(* Logix 5000 project; controller Electronic_Displays vendor 1 type 14 code 65 rev 17.4; software revision 17.01 *)
// Electronic Displays, Inc.
// Test PLC for Anybus Communicator

TASK MainTask (continuous, watchdog 500 ms) : MainProgram

MODULES
   Controller : vendor 1 type 14 code 65 (CompactLogixL35Controller 0, rev 17.4)
      LocalENB : 1769-L35E Ethernet Port (CompactLogixL35Ethernet 1, rev 17.2)
         LEDSIGN : ETHERNET-MODULE (Ethernet 192.168.1.11, rev 1.1, Output RPI 10 ms)   // RTA
      Local : CompactBus (CompactVirtualAdapter 3, rev 17.2, Input RPI 5 ms)
END_MODULES

TYPE LEDSIGN :
STRUCT
   Address : STRING;   // "00"=all signs "01"=sign address 1 "02"=sign address 2 etc... per protocol [must be two digits]
   CommandCode : STRING;   // "A"=write restart "B"=write variable "C"=special "D"=write no restart
   FileLabel : STRING;   // Default is = A
   Text1Message : STRING;   // Actual Text Line 1
   Text2Message : STRING;   // Actual Text Line 2
   Text3Message : STRING;   // Actual Text Line 3
   Text4Message : STRING;   // Actual Text Line 4
   TextFont : STRING;   // "0"=SS7 "1"=SF7 "2"=SF10 "3"=SS16 "4"=SF16
   TextColor : STRING;   // "0"=Red "1"=Green "2"=Yellow "3"=Rainbow
   TextAlign : STRING;   // "M"=middle line "T"=top line "B"=bottom line "F"=fill (best for variables) "L"=left "R"=right
   TextAttribute : STRING;   // "0"=flashing off "1"=flashing on "2"=wide off "3"=wide on "4"=bold off "5"=bold on
   TextEffect : STRING;   // "S"=scrolls "H"=hold "F"=flash "A"=slide up "B"=slide down "C"=slide left "D"=slide right "a"=roll up "b"=roll down "c"=roll left "d"=roll right
   TextSpeed : STRING;   // Options = 1 - 8, 3:Default 1=Fast 8=Slow
   TextPause : STRING;   // Options = 00 - 99, 02:Default defined in seconds [must be two digits] if not will not work!
   Variable1Name : STRING;   // Name of variable Default is = U
   Variable2Name : STRING;   // Name of variable Default is = V
   Variable3Name : STRING;   // Name of variable Default is = W
   Variable4Name : STRING;   // Name of variable Default is = X
   Variable1Value : STRING;   // Actual Variable1 to be Sent (text format)
   Variable2Value : STRING;   // Actual Variable2 to be Sent (text format)
   Variable3Value : STRING;   // Actual Variable3 to be Sent (text format)
   Variable4Value : STRING;   // Actual Variable4 to be Sent (text format)
   VariableFont : STRING;   // "0"=SS7 "1"=SF7 "2"=SF10 "3"=SS16 "4"=SF16
   VariableColor : STRING;   // "0"=Red "1"=Green "2"=Yellow "3"=Rainbow
   VariableAttribute : STRING;   // "0"=flashing off "1"=flashing on "2"=wide off "3"=wide on "4"=bold off "5"=bold on
   Packet1Sent : STRING;   // The actual packet sent to the sign. (Packet1)
   Packet2Sent : STRING;   // The actual packet sent to the sign. (Packet2)
   Packet3Sent : STRING;   // The actual packet sent to the sign. (Packet3)
   Packet4Sent : STRING;   // The actual packet sent to the sign. (Packet4)
   Packet5Sent : STRING;   // The actual packet sent to the sign. (Packet5)
   Packet6Sent : STRING;   // The actual packet sent to the sign. (Packet6)
   ExpertPacket1 : STRING;   // Raw Packet1 to be sent to sign for the expert users. (82 Characters max)
   ExpertPacket2 : STRING;   // Raw Packet2 to be sent to sign for the expert users. (82 Characters max)
   ExpertPacket3 : STRING;   // Raw Packet3 to be sent to sign for the expert users. (82 Characters max)
   ExpertPacket4 : STRING;   // Raw Packet4 to be sent to sign for the expert users. (82 Characters max)
   ExpertPacket5 : STRING;   // Raw Packet5 to be sent to sign for the expert users. (82 Characters max)
   ExpertPacket6 : STRING;   // Raw Packet6 to be sent to sign for the expert users. (82 Characters max)
END_STRUCT
END_TYPE

TYPE NUMSIGN :
STRUCT
   Address : STRING;   // "01"=sign address 1 "02"=sign address 2 etc... per protocol [must be two digits]
   NumberValue : DINT;   // Actual Number to Send to Sign (DINT Format)
   PacketSent : STRING;   // The actual packet sent to the sign.
END_STRUCT
END_TYPE

ADD_ON_INSTRUCTION ExpertSign   (* revision 1.0, ExecuteEnableInFalse *)
// Expert Mode
// Send Your Own
// Packets
// Revision note:
// Original Release
// 11-01-2012
// c.elston
VAR_IN_OUT
   ExpertPacket1 : STRING; {required}   // Raw Packet1 to be sent to sign for the expert users. (82 Characters max)
   ExpertPacket2 : STRING; {required}   // Raw Packet2 to be sent to sign for the expert users. (82 Characters max)
   ExpertPacket3 : STRING; {required}   // Raw Packet3 to be sent to sign for the expert users. (82 Characters max)
   ExpertPacket4 : STRING; {required}   // Raw Packet4 to be sent to sign for the expert users. (82 Characters max)
   ExpertPacket5 : STRING; {required}   // Raw Packet5 to be sent to sign for the expert users. (82 Characters max)
   ExpertPacket6 : STRING; {required}   // Raw Packet6 to be sent to sign for the expert users. (82 Characters max)
END_VAR
VAR_OUTPUT
   EN : BOOL; {visible}   // Instruction Interface Enable Bit
   DN : BOOL; {visible}   // Instruction Interface Done Bit
   ER : BOOL; {visible}   // Instruction Interface Error Bit
   IP : BOOL; {visible}   // Instruction Interface InProcess Bit
END_VAR
VAR_IN_OUT
   map_SignInput : SINT[32]; {required}   // Ethernet/IP LEDSIGN.I Data I/O Mapping
   map_SignOutput : SINT[496]; {required}   // Ethernet/IP LEDSIGN.O Data I/O Mapping
   Packet1Sent : STRING; {required}   // The actual packet sent to the sign (Packet1)
   Packet2Sent : STRING; {required}   // The actual packet sent to the sign (Packet2)
   Packet3Sent : STRING; {required}   // The actual packet sent to the sign (Packet3)
   Packet4Sent : STRING; {required}   // The actual packet sent to the sign (Packet4)
   Packet5Sent : STRING; {required}   // The actual packet sent to the sign (Packet5)
   Packet6Sent : STRING; {required}   // The actual packet sent to the sign (Packet6)
END_VAR
VAR
   SEQ : DINT;   // Sequence Number
   OktoCycle : BOOL;   // Ok to Cycle
   InCycle : BOOL;   // Incycle
   Error : BOOL;   // Error
   Enabled : BOOL;   // Enable ON Bit
   Done : BOOL;   // Done
   Disabled : BOOL;   // Disabled OFF Bit
   SignNULL : STRING;
   TotalPacketCount : DINT[7];   // Total Character Count
   Select : DINT;   // Packet Array Select
   PacketMax : DINT := 82;   // Max Packet Count
   PacketCount : DINT[7];
   Packet6Offset : DINT;
   Packet5Offset : DINT;
   Packet4Offset : DINT;
   Packet3Offset : DINT;
   Packet2Offset : DINT;
   Packet1Offset : DINT;
   Packet : STRING[7];   // Packet Array to send to sign
   SignExpertPacket6 : STRING;
   SignExpertPacket5 : STRING;
   SignExpertPacket4 : STRING;
   SignExpertPacket3 : STRING;
   SignExpertPacket2 : STRING;
   SignExpertPacket1 : STRING;
END_VAR

ROUTINE EnableInFalse   (* ladder *)
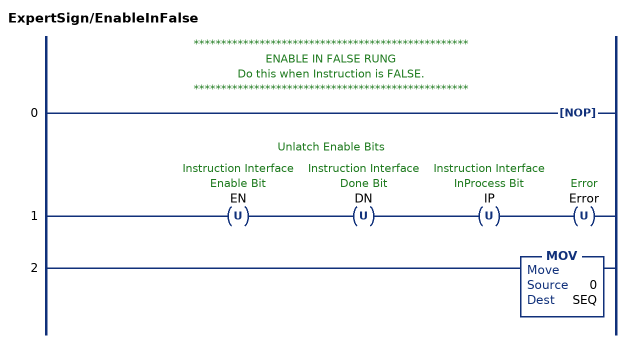
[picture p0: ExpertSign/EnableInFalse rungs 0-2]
   // **************************************************
   // ENABLE IN FALSE RUNG
   // Do this when Instruction is FALSE.
   // **************************************************
   0: NOP();
   // Unlatch Enable Bits
   1: OTU(EN)OTU(DN)OTU(IP)OTU(Error);
   2: MOV(0,SEQ);
END_ROUTINE

ROUTINE Logic   (* ladder *)
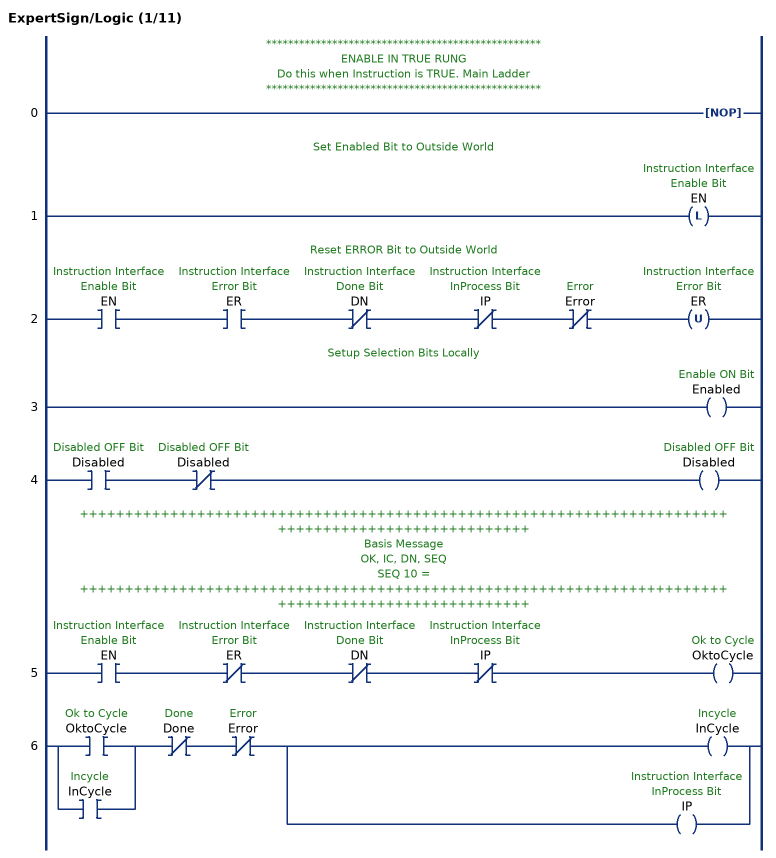
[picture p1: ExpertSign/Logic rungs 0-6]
   // **************************************************
   // ENABLE IN TRUE RUNG
   // Do this when Instruction is TRUE. Main Ladder
   // **************************************************
   0: NOP();
   // Set Enabled Bit to Outside World
   1: OTL(EN);
   // Reset ERROR Bit to Outside World
   2: XIC(EN)XIC(ER)XIO(DN)XIO(IP)XIO(Error)OTU(ER);
   // Setup Selection Bits Locally
   3: OTE(Enabled);
   4: XIC(Disabled)XIO(Disabled)OTE(Disabled);
   // ++++++++++++++++++++++++++++++++++++++++++++++++++++++++++++++++++++++++++++++++++++++++++++++++++++
   // Basis Message
   // OK, IC, DN, SEQ
   // SEQ 10 =
   // ++++++++++++++++++++++++++++++++++++++++++++++++++++++++++++++++++++++++++++++++++++++++++++++++++++
   5: XIC(EN)XIO(ER)XIO(DN)XIO(IP)OTE(OktoCycle);
   6: [XIC(OktoCycle) ,XIC(InCycle) ]XIO(Done)XIO(Error)[OTE(InCycle) ,OTE(IP) ];
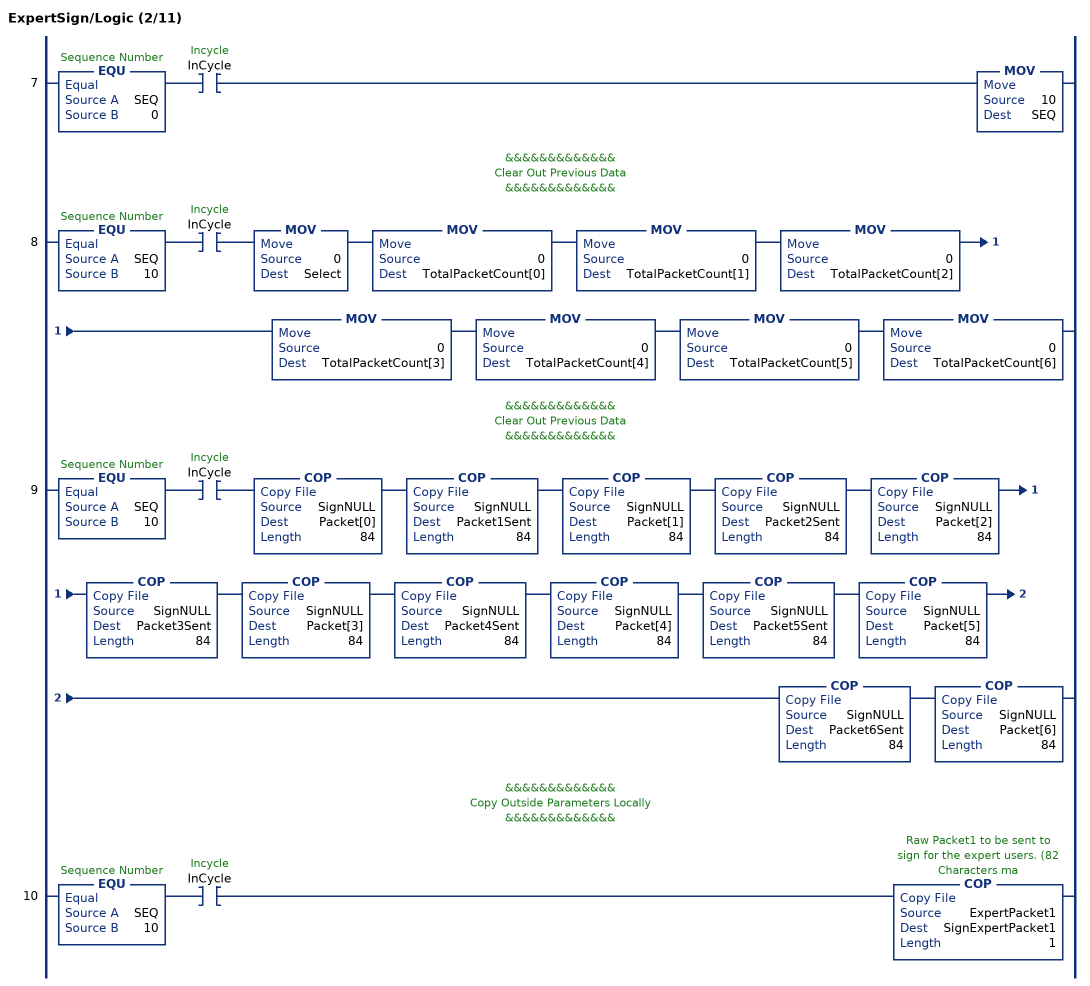
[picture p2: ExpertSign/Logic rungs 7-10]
   7: EQU(SEQ,0)XIC(InCycle)MOV(10,SEQ);
   // &&&&&&&&&&&&&
   // Clear Out Previous Data
   // &&&&&&&&&&&&&
   8: EQU(SEQ,10)XIC(InCycle)MOV(0,Select)MOV(0,TotalPacketCount[0])MOV(0,TotalPacketCount[1])MOV(0,TotalPacketCount[2])MOV(0,TotalPacketCount[3])MOV(0,TotalPacketCount[4])MOV(0,TotalPacketCount[5])MOV(0,TotalPacketCount[6]);
   // &&&&&&&&&&&&&
   // Clear Out Previous Data
   // &&&&&&&&&&&&&
   9: EQU(SEQ,10)XIC(InCycle)COP(SignNULL,Packet[0],84)COP(SignNULL,Packet1Sent,84)COP(SignNULL,Packet[1],84)COP(SignNULL,Packet2Sent,84)COP(SignNULL,Packet[2],84)COP(SignNULL,Packet3Sent,84)COP(SignNULL,Packet[3],84)COP(SignNULL,Packet4Sent,84)COP(SignNULL,Packet[4],84)COP(SignNULL,Packet5Sent,84)COP(SignNULL,Packet[5],84)COP(SignNULL,Packet6Sent,84)COP(SignNULL,Packet[6],84);
   // &&&&&&&&&&&&&
   // Copy Outside Parameters Locally
   // &&&&&&&&&&&&&
   10: EQU(SEQ,10)XIC(InCycle)COP(ExpertPacket1,SignExpertPacket1,1);
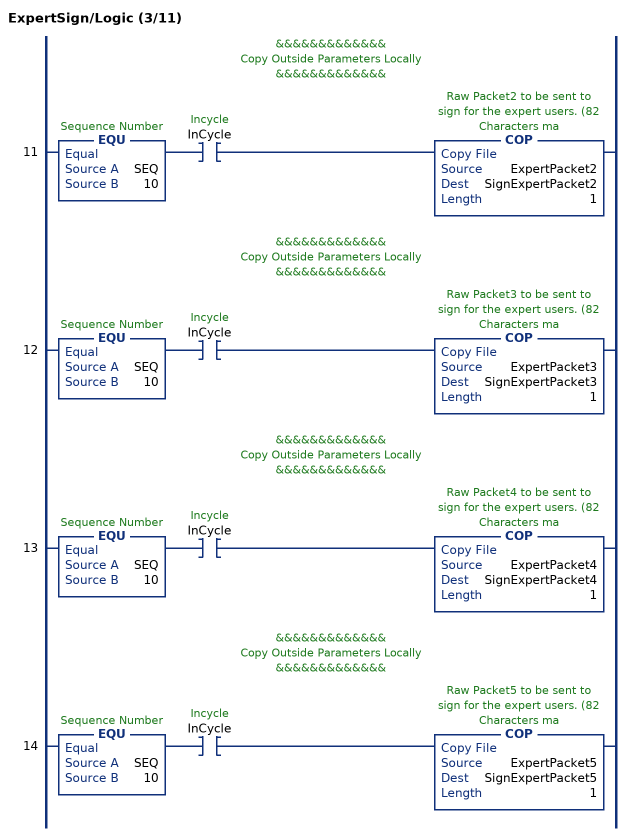
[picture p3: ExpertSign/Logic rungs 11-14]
   // &&&&&&&&&&&&&
   // Copy Outside Parameters Locally
   // &&&&&&&&&&&&&
   11: EQU(SEQ,10)XIC(InCycle)COP(ExpertPacket2,SignExpertPacket2,1);
   // &&&&&&&&&&&&&
   // Copy Outside Parameters Locally
   // &&&&&&&&&&&&&
   12: EQU(SEQ,10)XIC(InCycle)COP(ExpertPacket3,SignExpertPacket3,1);
   // &&&&&&&&&&&&&
   // Copy Outside Parameters Locally
   // &&&&&&&&&&&&&
   13: EQU(SEQ,10)XIC(InCycle)COP(ExpertPacket4,SignExpertPacket4,1);
   // &&&&&&&&&&&&&
   // Copy Outside Parameters Locally
   // &&&&&&&&&&&&&
   14: EQU(SEQ,10)XIC(InCycle)COP(ExpertPacket5,SignExpertPacket5,1);
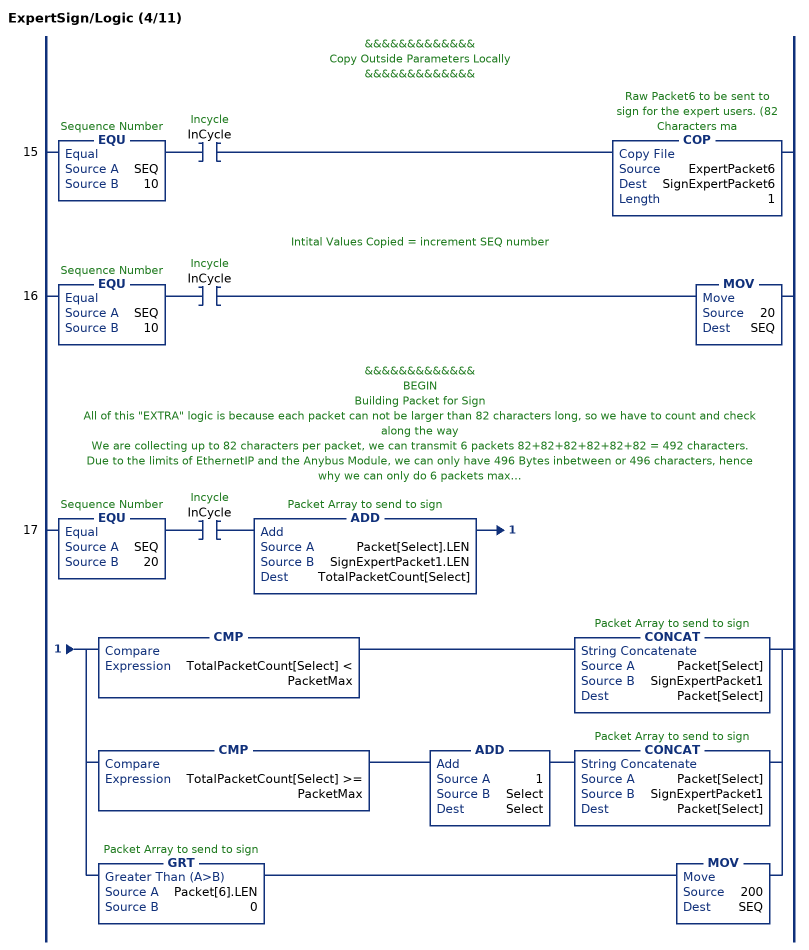
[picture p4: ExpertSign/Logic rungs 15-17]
   // &&&&&&&&&&&&&
   // Copy Outside Parameters Locally
   // &&&&&&&&&&&&&
   15: EQU(SEQ,10)XIC(InCycle)COP(ExpertPacket6,SignExpertPacket6,1);
   // Intital Values Copied = increment SEQ number
   16: EQU(SEQ,10)XIC(InCycle)MOV(20,SEQ);
   // &&&&&&&&&&&&&
   // BEGIN
   // Building Packet for Sign
   // All of this "EXTRA" logic is because each packet can not be larger than 82 characters long, so we have to count and check along the way
   // We are collecting up to 82 characters per packet, we can transmit 6 packets 82+82+82+82+82+82 = 492 characters.
   // Due to the limits of EthernetIP and the Anybus Module, we can only have 496 Bytes inbetween or 496 characters, hence why we can only do 6 packets max.
   // Once we exceed this, we will fault and ERROR trap any windy typing people.
   // In this instruction below, it's so small, we are only using 3 packets max.
   // &&&&&&&&&&&&&
   17: EQU(SEQ,20)XIC(InCycle)ADD(Packet[Select].LEN,SignExpertPacket1.LEN,TotalPacketCount[Select])[CMP(TotalPacketCount[Select] < PacketMax) CONCAT(Packet[Select],SignExpertPacket1,Packet[Select]) ,CMP(TotalPacketCount[Select] >= PacketMax) ADD(1,Select,Select) CONCAT(Packet[Select],SignExpertPacket1,Packet[Select]) ,GRT(Packet[6].LEN,0) MOV(200,SEQ) ];
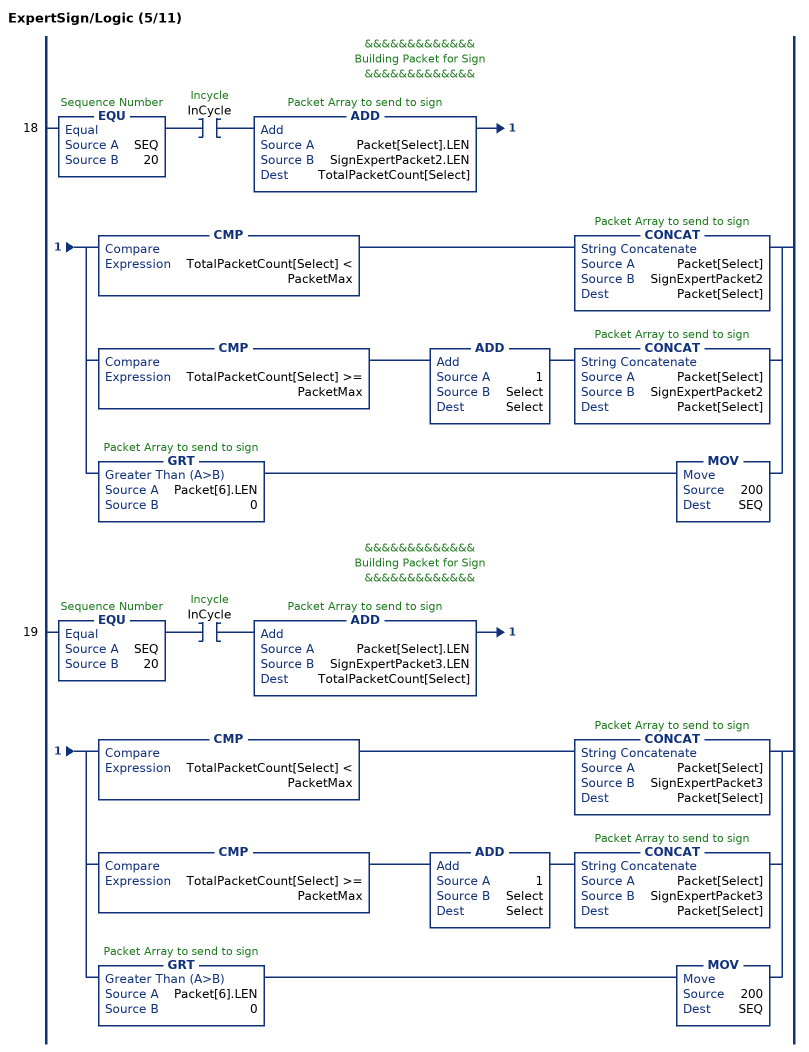
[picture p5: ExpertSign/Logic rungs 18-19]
   // &&&&&&&&&&&&&
   // Building Packet for Sign
   // &&&&&&&&&&&&&
   18: EQU(SEQ,20)XIC(InCycle)ADD(Packet[Select].LEN,SignExpertPacket2.LEN,TotalPacketCount[Select])[CMP(TotalPacketCount[Select] < PacketMax) CONCAT(Packet[Select],SignExpertPacket2,Packet[Select]) ,CMP(TotalPacketCount[Select] >= PacketMax) ADD(1,Select,Select) CONCAT(Packet[Select],SignExpertPacket2,Packet[Select]) ,GRT(Packet[6].LEN,0) MOV(200,SEQ) ];
   // &&&&&&&&&&&&&
   // Building Packet for Sign
   // &&&&&&&&&&&&&
   19: EQU(SEQ,20)XIC(InCycle)ADD(Packet[Select].LEN,SignExpertPacket3.LEN,TotalPacketCount[Select])[CMP(TotalPacketCount[Select] < PacketMax) CONCAT(Packet[Select],SignExpertPacket3,Packet[Select]) ,CMP(TotalPacketCount[Select] >= PacketMax) ADD(1,Select,Select) CONCAT(Packet[Select],SignExpertPacket3,Packet[Select]) ,GRT(Packet[6].LEN,0) MOV(200,SEQ) ];
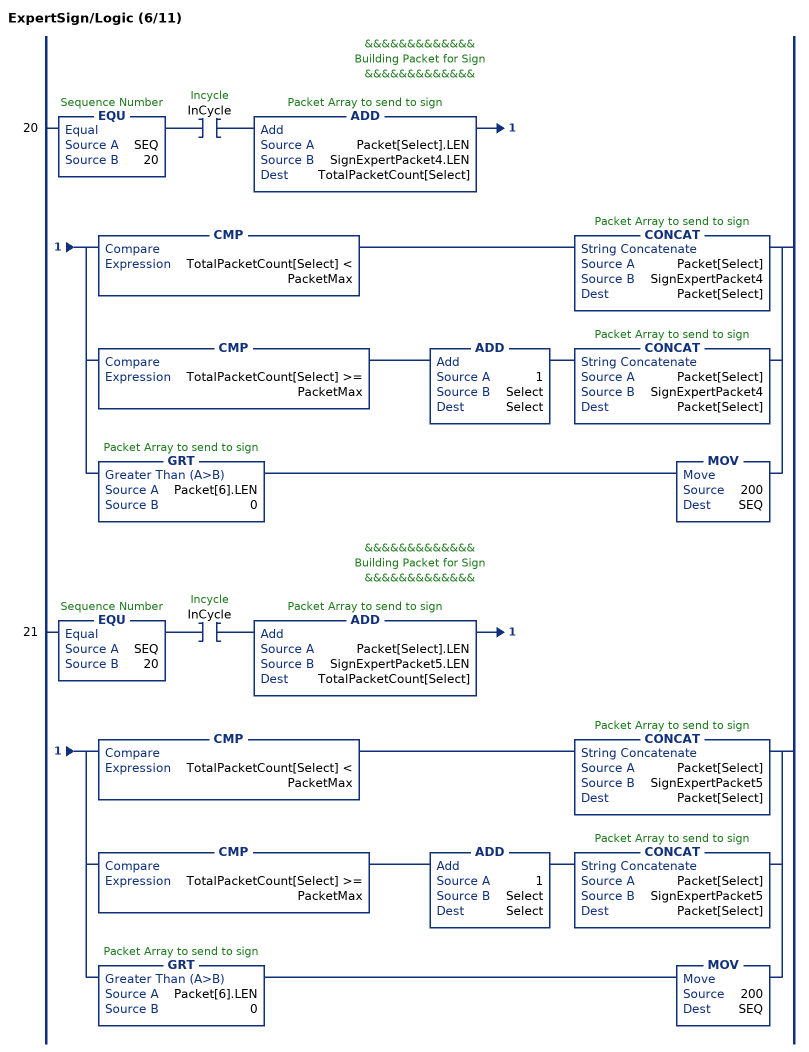
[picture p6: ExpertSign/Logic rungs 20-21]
   // &&&&&&&&&&&&&
   // Building Packet for Sign
   // &&&&&&&&&&&&&
   20: EQU(SEQ,20)XIC(InCycle)ADD(Packet[Select].LEN,SignExpertPacket4.LEN,TotalPacketCount[Select])[CMP(TotalPacketCount[Select] < PacketMax) CONCAT(Packet[Select],SignExpertPacket4,Packet[Select]) ,CMP(TotalPacketCount[Select] >= PacketMax) ADD(1,Select,Select) CONCAT(Packet[Select],SignExpertPacket4,Packet[Select]) ,GRT(Packet[6].LEN,0) MOV(200,SEQ) ];
   // &&&&&&&&&&&&&
   // Building Packet for Sign
   // &&&&&&&&&&&&&
   21: EQU(SEQ,20)XIC(InCycle)ADD(Packet[Select].LEN,SignExpertPacket5.LEN,TotalPacketCount[Select])[CMP(TotalPacketCount[Select] < PacketMax) CONCAT(Packet[Select],SignExpertPacket5,Packet[Select]) ,CMP(TotalPacketCount[Select] >= PacketMax) ADD(1,Select,Select) CONCAT(Packet[Select],SignExpertPacket5,Packet[Select]) ,GRT(Packet[6].LEN,0) MOV(200,SEQ) ];
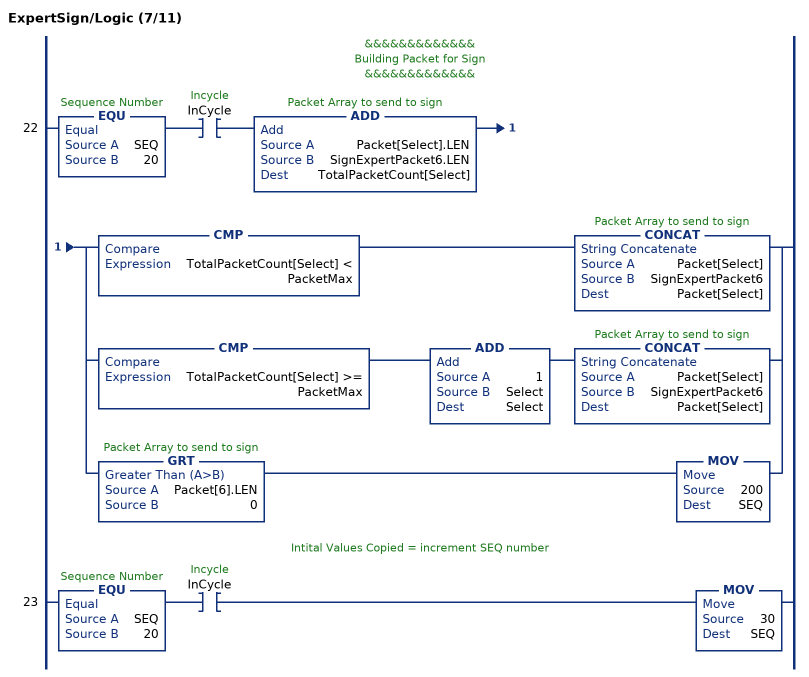
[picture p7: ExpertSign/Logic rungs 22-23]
   // &&&&&&&&&&&&&
   // Building Packet for Sign
   // &&&&&&&&&&&&&
   22: EQU(SEQ,20)XIC(InCycle)ADD(Packet[Select].LEN,SignExpertPacket6.LEN,TotalPacketCount[Select])[CMP(TotalPacketCount[Select] < PacketMax) CONCAT(Packet[Select],SignExpertPacket6,Packet[Select]) ,CMP(TotalPacketCount[Select] >= PacketMax) ADD(1,Select,Select) CONCAT(Packet[Select],SignExpertPacket6,Packet[Select]) ,GRT(Packet[6].LEN,0) MOV(200,SEQ) ];
   // Intital Values Copied = increment SEQ number
   23: EQU(SEQ,20)XIC(InCycle)MOV(30,SEQ);
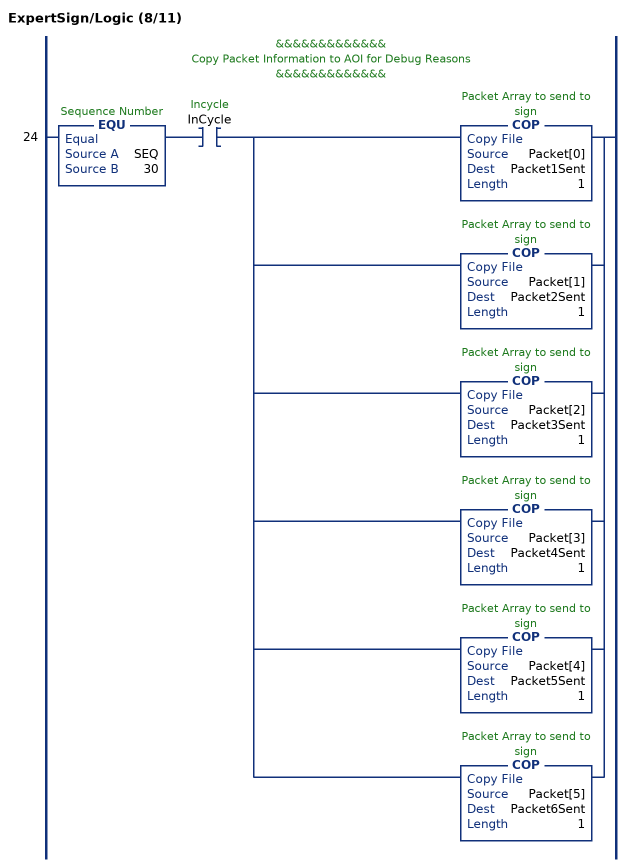
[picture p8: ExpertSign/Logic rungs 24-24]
   // &&&&&&&&&&&&&
   // Copy Packet Information to AOI for Debug Reasons
   // &&&&&&&&&&&&&
   24: EQU(SEQ,30)XIC(InCycle)[COP(Packet[0],Packet1Sent,1) ,COP(Packet[1],Packet2Sent,1) ,COP(Packet[2],Packet3Sent,1) ,COP(Packet[3],Packet4Sent,1) ,COP(Packet[4],Packet5Sent,1) ,COP(Packet[5],Packet6Sent,1) ];
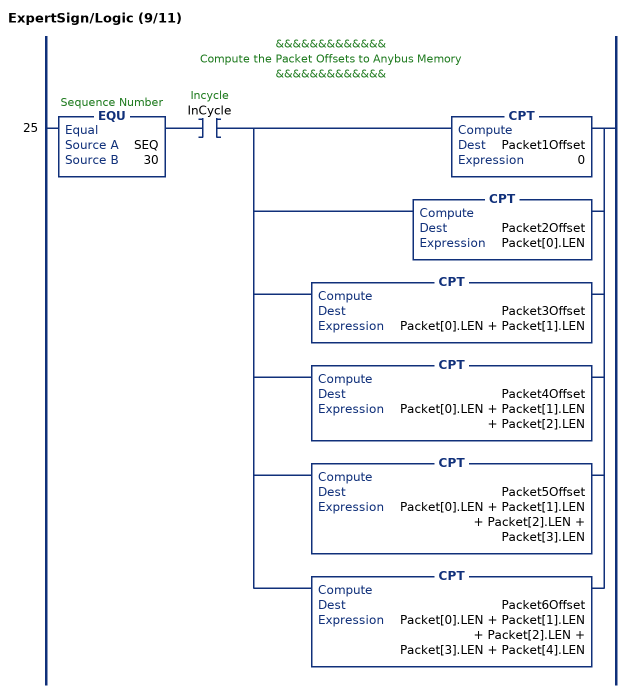
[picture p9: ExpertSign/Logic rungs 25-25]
   // &&&&&&&&&&&&&
   // Compute the Packet Offsets to Anybus Memory
   // &&&&&&&&&&&&&
   25: EQU(SEQ,30)XIC(InCycle)[CPT(Packet1Offset,0) ,CPT(Packet2Offset,Packet[0].LEN) ,CPT(Packet3Offset,Packet[0].LEN + Packet[1].LEN) ,CPT(Packet4Offset,Packet[0].LEN + Packet[1].LEN + Packet[2].LEN) ,CPT(Packet5Offset,Packet[0].LEN + Packet[1].LEN + Packet[2].LEN + Packet[3].LEN) ,CPT(Packet6Offset,Packet[0].LEN + Packet[1].LEN + Packet[2].LEN + Packet[3].LEN + Packet[4].LEN) ];
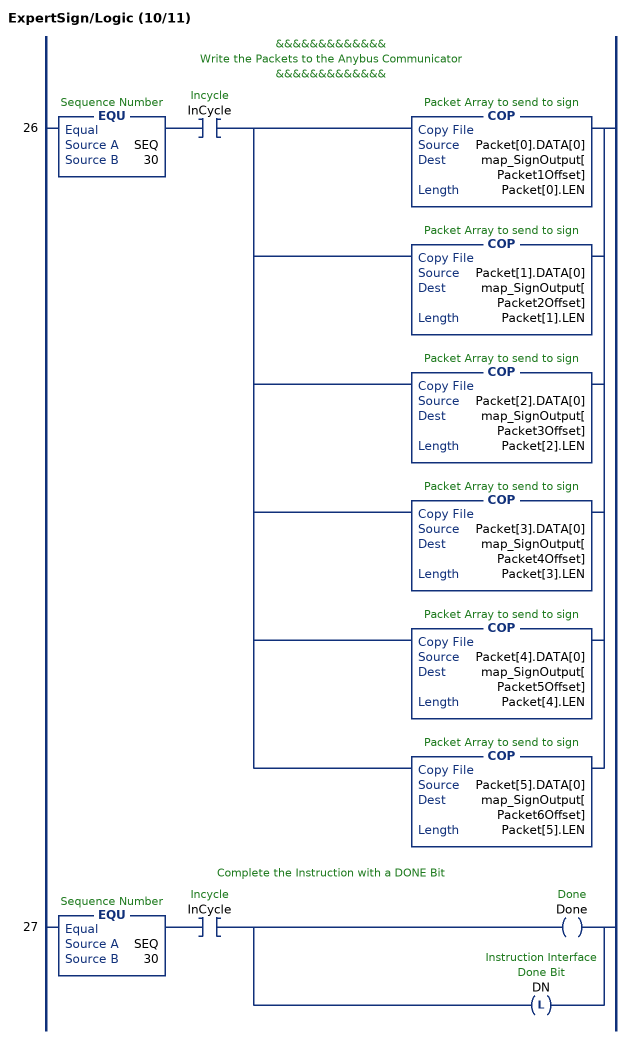
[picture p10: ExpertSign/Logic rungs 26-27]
   // &&&&&&&&&&&&&
   // Write the Packets to the Anybus Communicator
   // &&&&&&&&&&&&&
   26: EQU(SEQ,30)XIC(InCycle)[COP(Packet[0].DATA[0],map_SignOutput[Packet1Offset],Packet[0].LEN) ,COP(Packet[1].DATA[0],map_SignOutput[Packet2Offset],Packet[1].LEN) ,COP(Packet[2].DATA[0],map_SignOutput[Packet3Offset],Packet[2].LEN) ,COP(Packet[3].DATA[0],map_SignOutput[Packet4Offset],Packet[3].LEN) ,COP(Packet[4].DATA[0],map_SignOutput[Packet5Offset],Packet[4].LEN) ,COP(Packet[5].DATA[0],map_SignOutput[Packet6Offset],Packet[5].LEN) ];
   // Complete the Instruction with a DONE Bit
   27: EQU(SEQ,30)XIC(InCycle)[OTE(Done) ,OTL(DN) ];
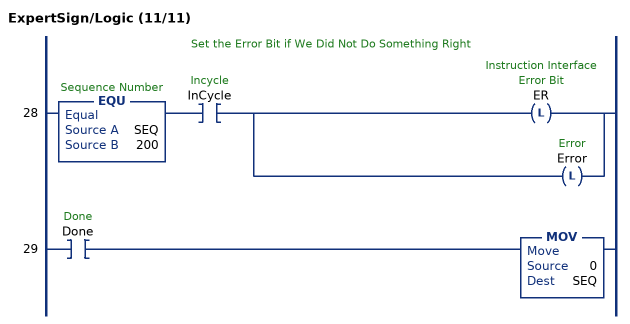
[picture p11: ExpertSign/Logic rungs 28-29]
   // Set the Error Bit if We Did Not Do Something Right
   28: EQU(SEQ,200)XIC(InCycle)[OTL(ER) ,OTL(Error) ];
   29: XIC(Done)MOV(0,SEQ);
END_ROUTINE
END_ADD_ON_INSTRUCTION

ADD_ON_INSTRUCTION ResetSign   (* revision 1.0, ExecuteEnableInFalse *)
// Reset Sign
// Erases All
// Variable Memory
// Revision note:
// Original Release
// 11-01-2012
// c.elston
VAR_IN_OUT
   Address : STRING; {required}   // "00" = all signs "01" = address 01 "02" = address 02 etc...(see protocol)
END_VAR
VAR_OUTPUT
   EN : BOOL; {visible}   // Instruction Interface Enable Bit
   DN : BOOL; {visible}   // Instruction Interface Done Bit
   ER : BOOL; {visible}   // Instruction Interface Error Bit
   IP : BOOL; {visible}   // Instruction Interface InProcess Bit
END_VAR
VAR_IN_OUT
   map_SignInput : SINT[32]; {required}   // Ethernet/IP LEDSIGN.I Data I/O Mapping
   map_SignOutput : SINT[496]; {required}   // Ethernet/IP LEDSIGN.O Data I/O Mapping
   Packet1Sent : STRING; {required}   // The actual packet sent to the sign (Packet1)
   Packet2Sent : STRING; {required}   // The actual packet sent to the sign (Packet2)
   Packet3Sent : STRING; {required}   // The actual packet sent to the sign (Packet3)
END_VAR
VAR
   SEQ : DINT;   // Sequence Number
   OktoCycle : BOOL;   // Ok to Cycle
   InCycle : BOOL;   // Incycle
   Error : BOOL;   // Error
   Enabled : BOOL;   // Enable ON Bit
   Done : BOOL;   // Done
   Disabled : BOOL;   // Disabled OFF Bit
   SignETX : STRING := '^C';   // DO NOT EDIT = ^C
   SignFileLabel : STRING;
   SignSOH : STRING := '^A';   // DO NOT EDIT = ^A
   SignAddress : STRING;
   SignSTX : STRING := '^B';   // DO NOT EDIT = ^B
   SignNULL : STRING;
   SignResetMemoryCommand : STRING := 'CM';   // DO NOT EDIT = SM
   SignCommandCode : STRING := 'C';   // DO NOT EDIT = C
   TotalPacketCount : DINT[7];   // Total Character Count
   Select : DINT;   // Packet Array Select
   PacketMax : DINT := 82;   // Max Packet Count
   PacketCount : DINT[7];
   Packet6Offset : DINT;
   Packet5Offset : DINT;
   Packet4Offset : DINT;
   Packet3Offset : DINT;
   Packet2Offset : DINT;
   Packet1Offset : DINT;
   Packet : STRING[7];   // Packet Array to send to sign
END_VAR

ROUTINE EnableInFalse   (* ladder *)
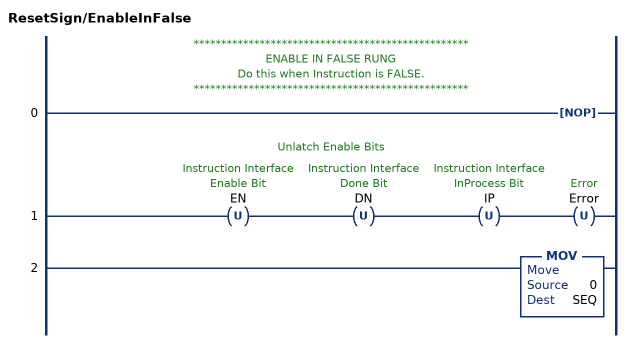
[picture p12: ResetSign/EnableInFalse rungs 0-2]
   // **************************************************
   // ENABLE IN FALSE RUNG
   // Do this when Instruction is FALSE.
   // **************************************************
   0: NOP();
   // Unlatch Enable Bits
   1: OTU(EN)OTU(DN)OTU(IP)OTU(Error);
   2: MOV(0,SEQ);
END_ROUTINE

ROUTINE Logic   (* ladder *)
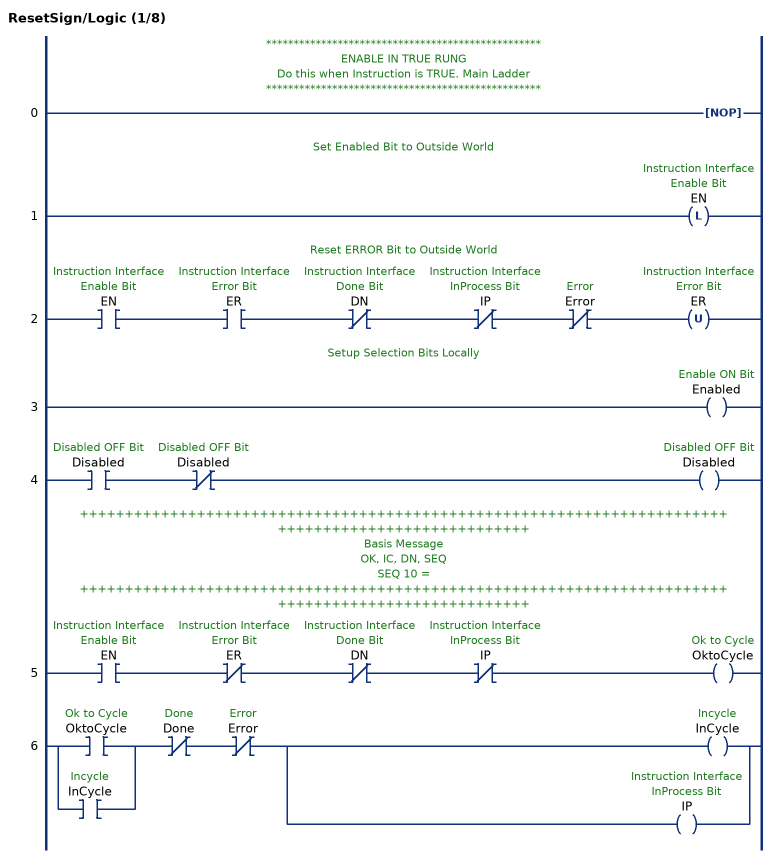
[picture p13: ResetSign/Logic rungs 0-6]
   // **************************************************
   // ENABLE IN TRUE RUNG
   // Do this when Instruction is TRUE. Main Ladder
   // **************************************************
   0: NOP();
   // Set Enabled Bit to Outside World
   1: OTL(EN);
   // Reset ERROR Bit to Outside World
   2: XIC(EN)XIC(ER)XIO(DN)XIO(IP)XIO(Error)OTU(ER);
   // Setup Selection Bits Locally
   3: OTE(Enabled);
   4: XIC(Disabled)XIO(Disabled)OTE(Disabled);
   // ++++++++++++++++++++++++++++++++++++++++++++++++++++++++++++++++++++++++++++++++++++++++++++++++++++
   // Basis Message
   // OK, IC, DN, SEQ
   // SEQ 10 =
   // ++++++++++++++++++++++++++++++++++++++++++++++++++++++++++++++++++++++++++++++++++++++++++++++++++++
   5: XIC(EN)XIO(ER)XIO(DN)XIO(IP)OTE(OktoCycle);
   6: [XIC(OktoCycle) ,XIC(InCycle) ]XIO(Done)XIO(Error)[OTE(InCycle) ,OTE(IP) ];
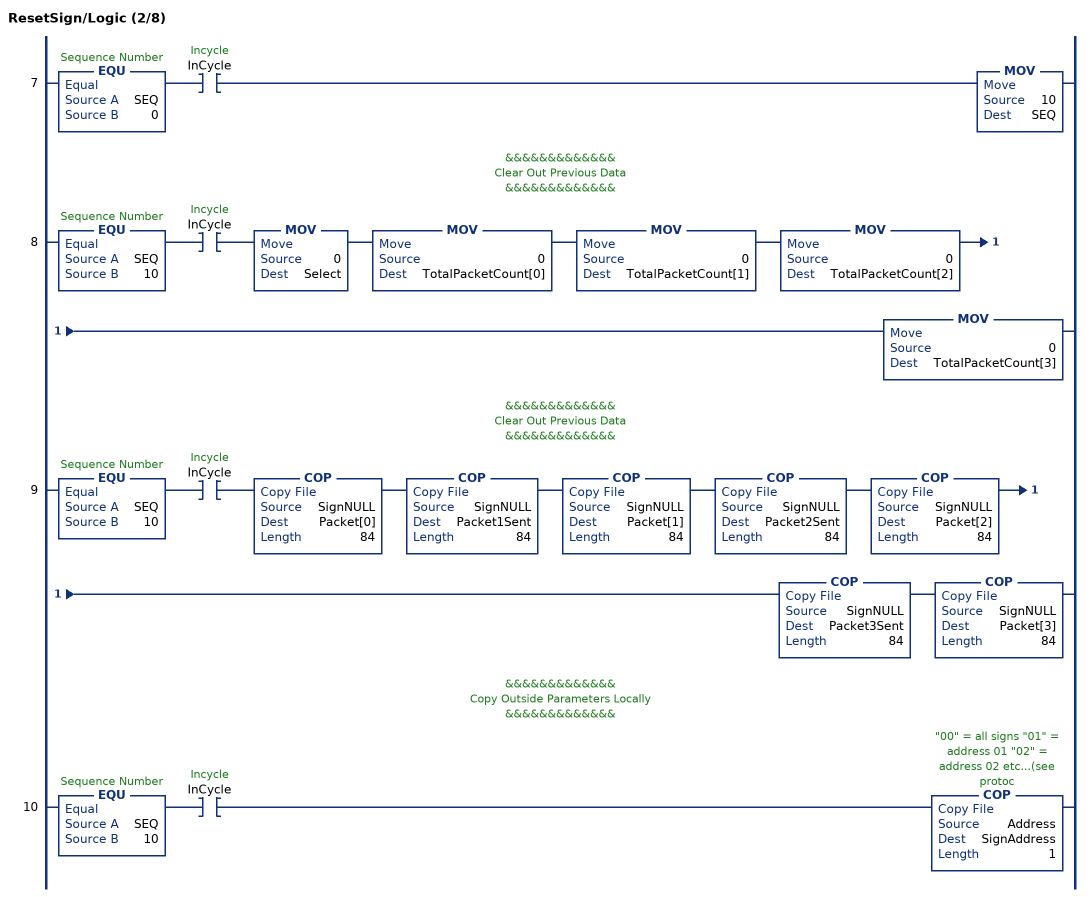
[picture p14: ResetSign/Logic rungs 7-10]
   7: EQU(SEQ,0)XIC(InCycle)MOV(10,SEQ);
   // &&&&&&&&&&&&&
   // Clear Out Previous Data
   // &&&&&&&&&&&&&
   8: EQU(SEQ,10)XIC(InCycle)MOV(0,Select)MOV(0,TotalPacketCount[0])MOV(0,TotalPacketCount[1])MOV(0,TotalPacketCount[2])MOV(0,TotalPacketCount[3]);
   // &&&&&&&&&&&&&
   // Clear Out Previous Data
   // &&&&&&&&&&&&&
   9: EQU(SEQ,10)XIC(InCycle)COP(SignNULL,Packet[0],84)COP(SignNULL,Packet1Sent,84)COP(SignNULL,Packet[1],84)COP(SignNULL,Packet2Sent,84)COP(SignNULL,Packet[2],84)COP(SignNULL,Packet3Sent,84)COP(SignNULL,Packet[3],84);
   // &&&&&&&&&&&&&
   // Copy Outside Parameters Locally
   // &&&&&&&&&&&&&
   10: EQU(SEQ,10)XIC(InCycle)COP(Address,SignAddress,1);
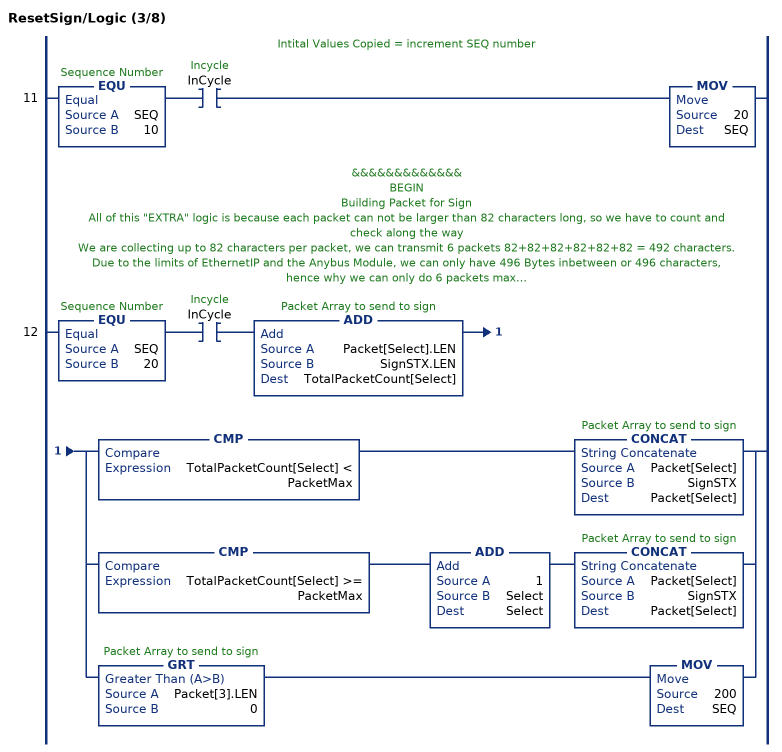
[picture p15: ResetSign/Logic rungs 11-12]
   // Intital Values Copied = increment SEQ number
   11: EQU(SEQ,10)XIC(InCycle)MOV(20,SEQ);
   // &&&&&&&&&&&&&
   // BEGIN
   // Building Packet for Sign
   // All of this "EXTRA" logic is because each packet can not be larger than 82 characters long, so we have to count and check along the way
   // We are collecting up to 82 characters per packet, we can transmit 6 packets 82+82+82+82+82+82 = 492 characters.
   // Due to the limits of EthernetIP and the Anybus Module, we can only have 496 Bytes inbetween or 496 characters, hence why we can only do 6 packets max.
   // Once we exceed this, we will fault and ERROR trap any windy typing people.
   // In this instruction below, it's so small, we are only using 3 packets max.
   // &&&&&&&&&&&&&
   12: EQU(SEQ,20)XIC(InCycle)ADD(Packet[Select].LEN,SignSTX.LEN,TotalPacketCount[Select])[CMP(TotalPacketCount[Select] < PacketMax) CONCAT(Packet[Select],SignSTX,Packet[Select]) ,CMP(TotalPacketCount[Select] >= PacketMax) ADD(1,Select,Select) CONCAT(Packet[Select],SignSTX,Packet[Select]) ,GRT(Packet[3].LEN,0) MOV(200,SEQ) ];
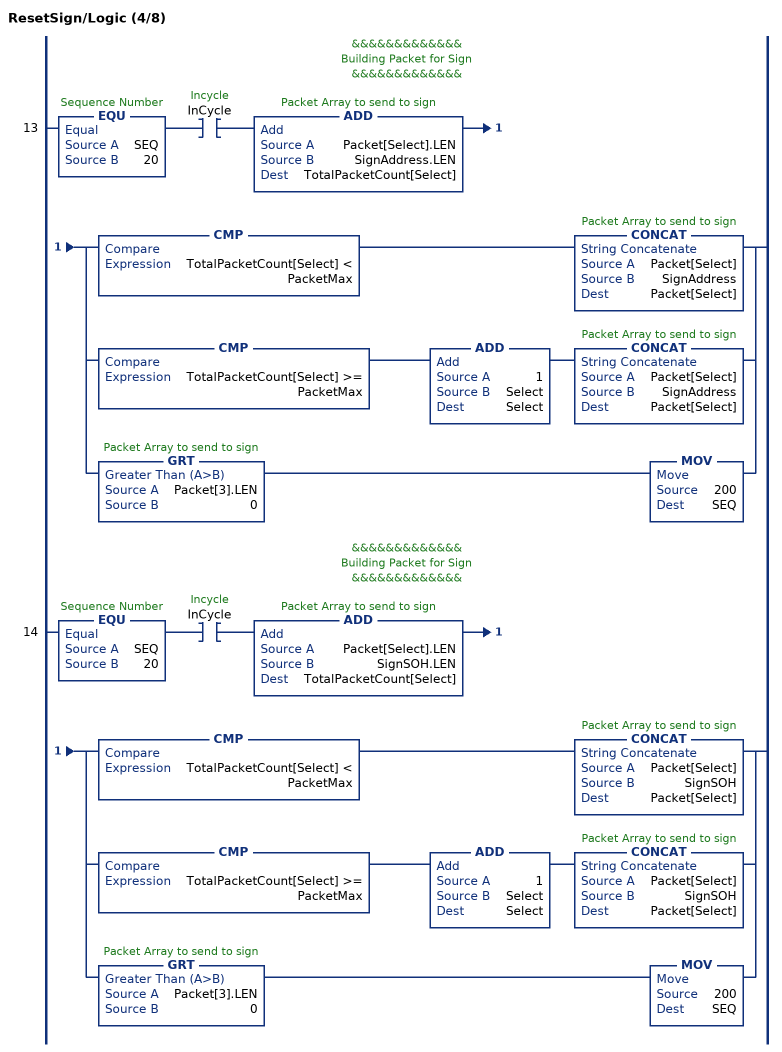
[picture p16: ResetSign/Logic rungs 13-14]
   // &&&&&&&&&&&&&
   // Building Packet for Sign
   // &&&&&&&&&&&&&
   13: EQU(SEQ,20)XIC(InCycle)ADD(Packet[Select].LEN,SignAddress.LEN,TotalPacketCount[Select])[CMP(TotalPacketCount[Select] < PacketMax) CONCAT(Packet[Select],SignAddress,Packet[Select]) ,CMP(TotalPacketCount[Select] >= PacketMax) ADD(1,Select,Select) CONCAT(Packet[Select],SignAddress,Packet[Select]) ,GRT(Packet[3].LEN,0) MOV(200,SEQ) ];
   // &&&&&&&&&&&&&
   // Building Packet for Sign
   // &&&&&&&&&&&&&
   14: EQU(SEQ,20)XIC(InCycle)ADD(Packet[Select].LEN,SignSOH.LEN,TotalPacketCount[Select])[CMP(TotalPacketCount[Select] < PacketMax) CONCAT(Packet[Select],SignSOH,Packet[Select]) ,CMP(TotalPacketCount[Select] >= PacketMax) ADD(1,Select,Select) CONCAT(Packet[Select],SignSOH,Packet[Select]) ,GRT(Packet[3].LEN,0) MOV(200,SEQ) ];
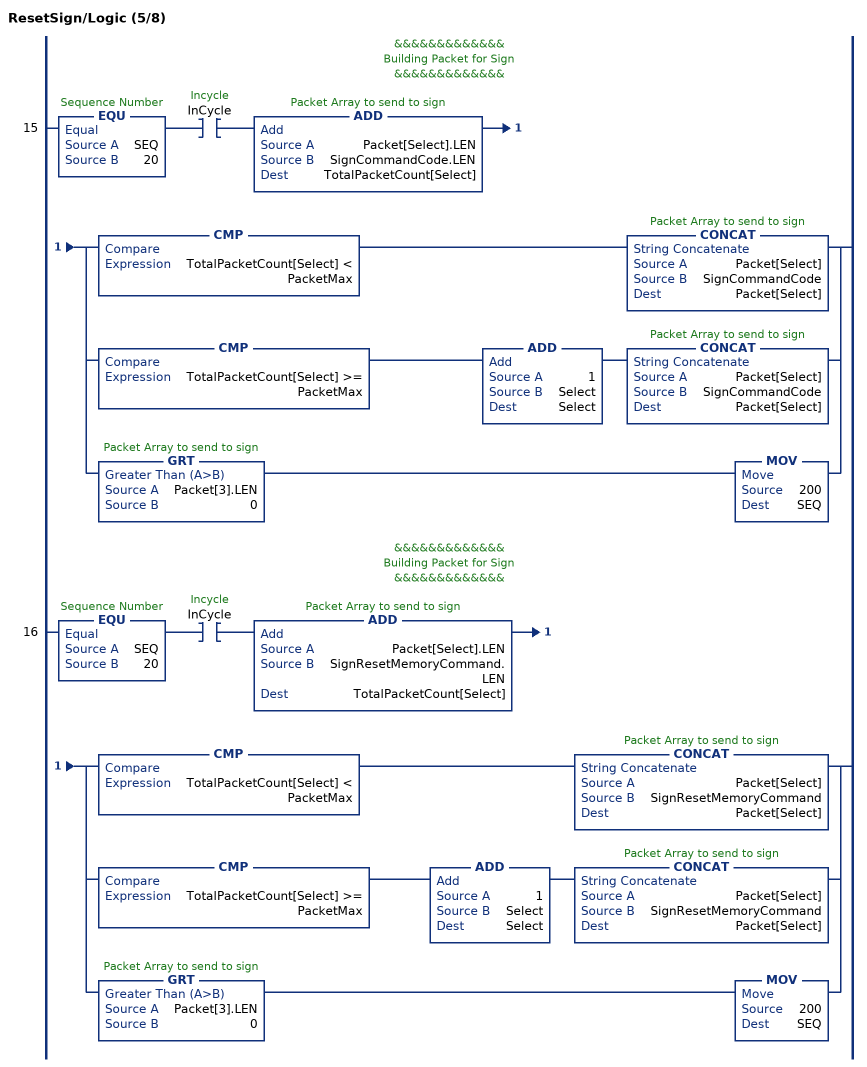
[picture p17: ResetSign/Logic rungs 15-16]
   // &&&&&&&&&&&&&
   // Building Packet for Sign
   // &&&&&&&&&&&&&
   15: EQU(SEQ,20)XIC(InCycle)ADD(Packet[Select].LEN,SignCommandCode.LEN,TotalPacketCount[Select])[CMP(TotalPacketCount[Select] < PacketMax) CONCAT(Packet[Select],SignCommandCode,Packet[Select]) ,CMP(TotalPacketCount[Select] >= PacketMax) ADD(1,Select,Select) CONCAT(Packet[Select],SignCommandCode,Packet[Select]) ,GRT(Packet[3].LEN,0) MOV(200,SEQ) ];
   // &&&&&&&&&&&&&
   // Building Packet for Sign
   // &&&&&&&&&&&&&
   16: EQU(SEQ,20)XIC(InCycle)ADD(Packet[Select].LEN,SignResetMemoryCommand.LEN,TotalPacketCount[Select])[CMP(TotalPacketCount[Select] < PacketMax) CONCAT(Packet[Select],SignResetMemoryCommand,Packet[Select]) ,CMP(TotalPacketCount[Select] >= PacketMax) ADD(1,Select,Select) CONCAT(Packet[Select],SignResetMemoryCommand,Packet[Select]) ,GRT(Packet[3].LEN,0) MOV(200,SEQ) ];
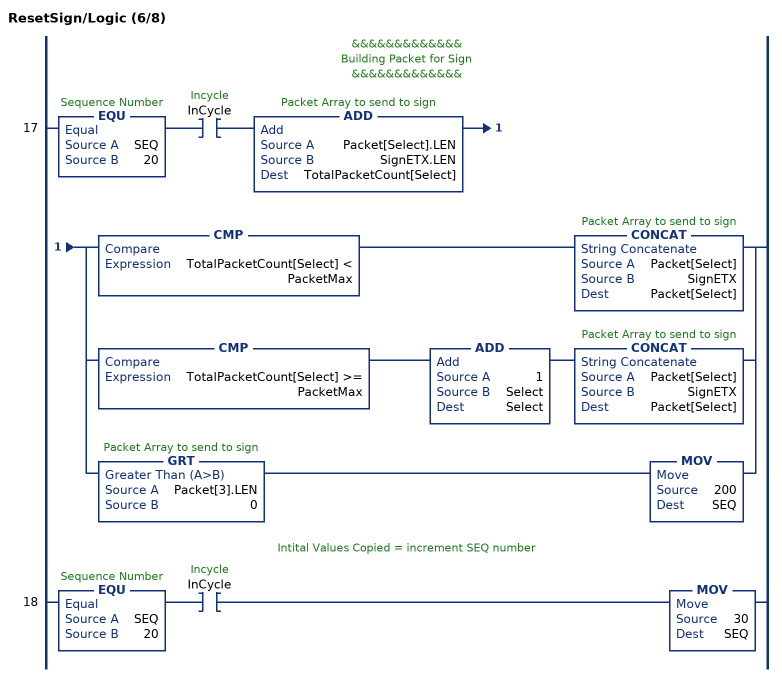
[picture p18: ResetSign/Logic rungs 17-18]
   // &&&&&&&&&&&&&
   // Building Packet for Sign
   // &&&&&&&&&&&&&
   17: EQU(SEQ,20)XIC(InCycle)ADD(Packet[Select].LEN,SignETX.LEN,TotalPacketCount[Select])[CMP(TotalPacketCount[Select] < PacketMax) CONCAT(Packet[Select],SignETX,Packet[Select]) ,CMP(TotalPacketCount[Select] >= PacketMax) ADD(1,Select,Select) CONCAT(Packet[Select],SignETX,Packet[Select]) ,GRT(Packet[3].LEN,0) MOV(200,SEQ) ];
   // Intital Values Copied = increment SEQ number
   18: EQU(SEQ,20)XIC(InCycle)MOV(30,SEQ);
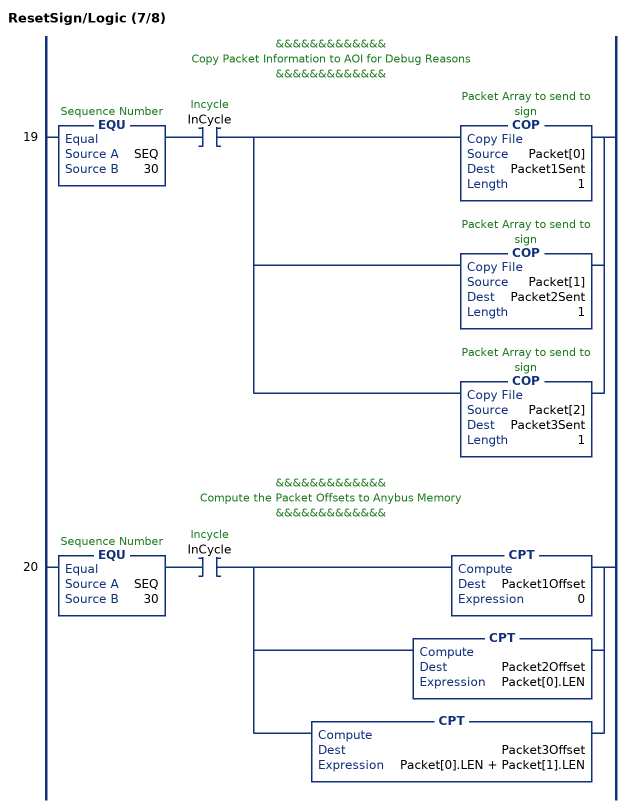
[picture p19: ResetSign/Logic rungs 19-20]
   // &&&&&&&&&&&&&
   // Copy Packet Information to AOI for Debug Reasons
   // &&&&&&&&&&&&&
   19: EQU(SEQ,30)XIC(InCycle)[COP(Packet[0],Packet1Sent,1) ,COP(Packet[1],Packet2Sent,1) ,COP(Packet[2],Packet3Sent,1) ];
   // &&&&&&&&&&&&&
   // Compute the Packet Offsets to Anybus Memory
   // &&&&&&&&&&&&&
   20: EQU(SEQ,30)XIC(InCycle)[CPT(Packet1Offset,0) ,CPT(Packet2Offset,Packet[0].LEN) ,CPT(Packet3Offset,Packet[0].LEN + Packet[1].LEN) ];
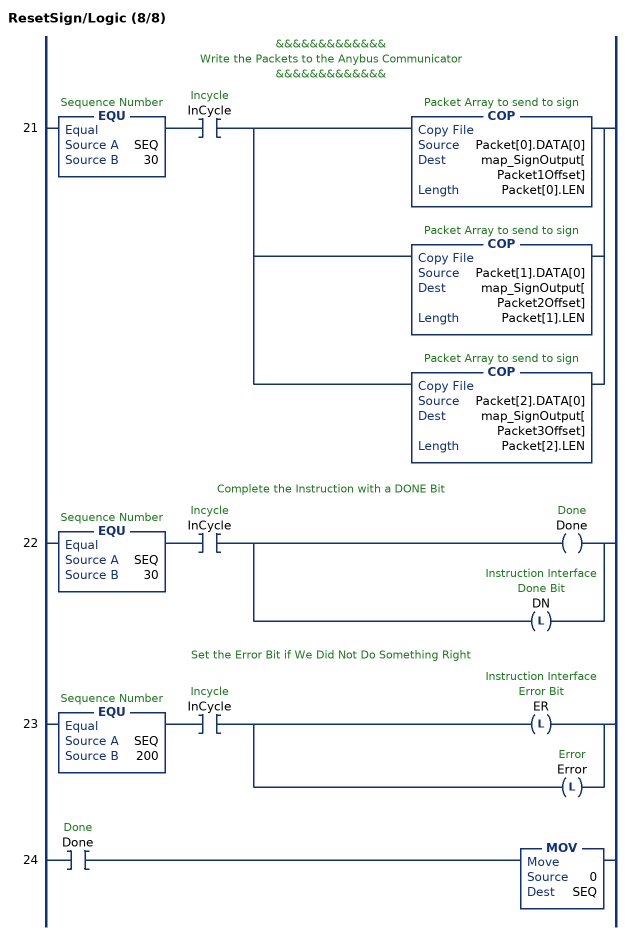
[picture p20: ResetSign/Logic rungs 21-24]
   // &&&&&&&&&&&&&
   // Write the Packets to the Anybus Communicator
   // &&&&&&&&&&&&&
   21: EQU(SEQ,30)XIC(InCycle)[COP(Packet[0].DATA[0],map_SignOutput[Packet1Offset],Packet[0].LEN) ,COP(Packet[1].DATA[0],map_SignOutput[Packet2Offset],Packet[1].LEN) ,COP(Packet[2].DATA[0],map_SignOutput[Packet3Offset],Packet[2].LEN) ];
   // Complete the Instruction with a DONE Bit
   22: EQU(SEQ,30)XIC(InCycle)[OTE(Done) ,OTL(DN) ];
   // Set the Error Bit if We Did Not Do Something Right
   23: EQU(SEQ,200)XIC(InCycle)[OTL(ER) ,OTL(Error) ];
   24: XIC(Done)MOV(0,SEQ);
END_ROUTINE
END_ADD_ON_INSTRUCTION
